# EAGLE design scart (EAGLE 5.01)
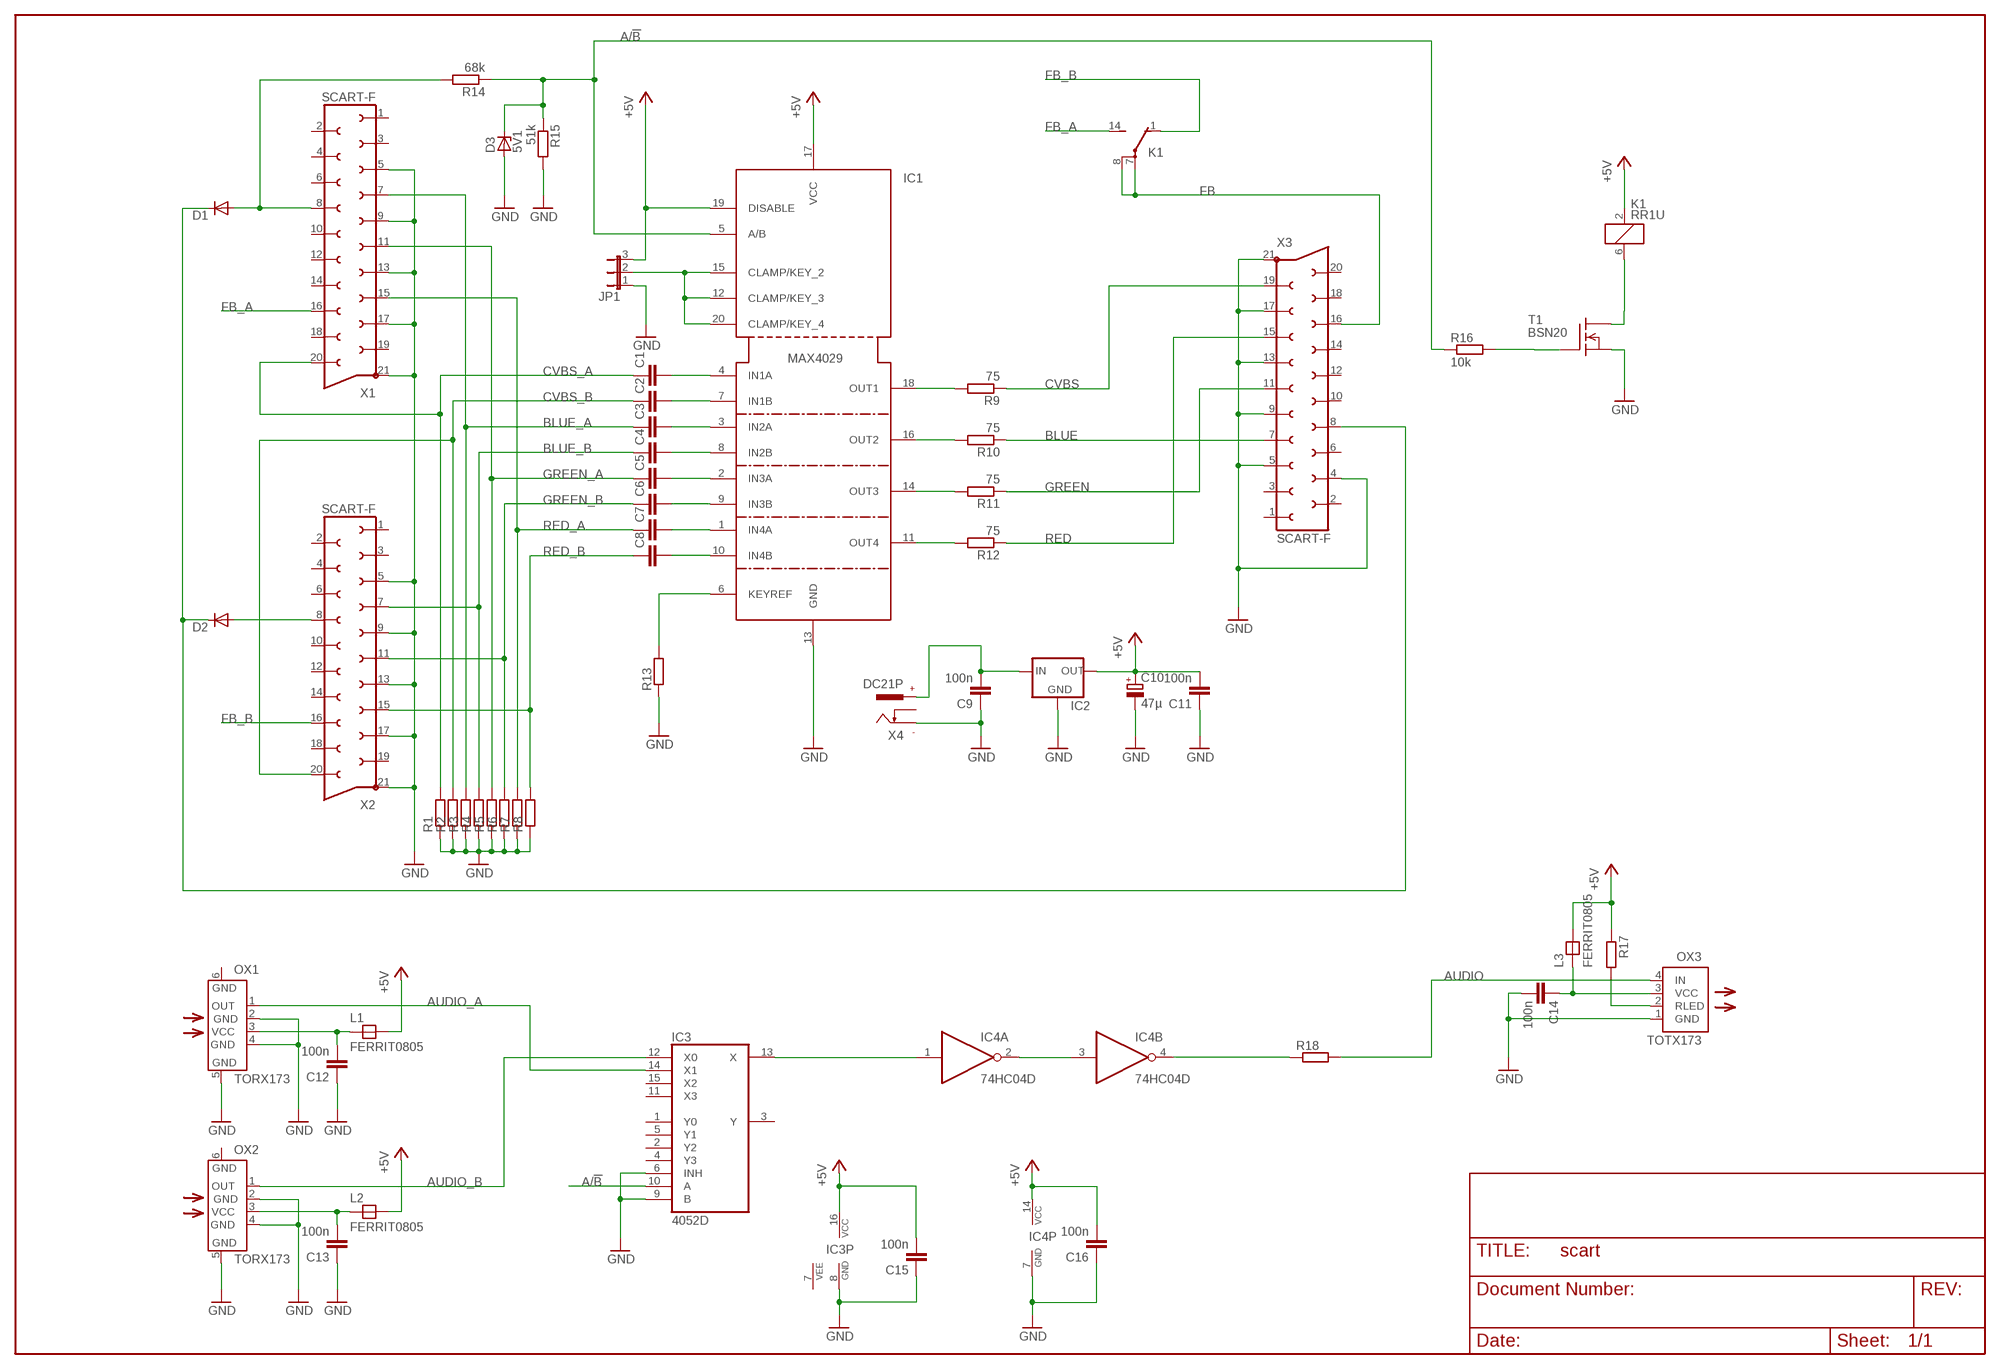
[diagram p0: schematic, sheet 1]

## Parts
C1  C-EUC0805  [C0805]
C2  C-EUC0805  [C0805]
C3  C-EUC0805  [C0805]
C4  C-EUC0805  [C0805]
C5  C-EUC0805  [C0805]
C6  C-EUC0805  [C0805]
C7  C-EUC0805  [C0805]
C8  C-EUC0805  [C0805]
C9  100n  C-EUC0805  [C0805]
C10  47µ  CPOL-EUD/7343-31W  [D/7343-31W]
C11  100n  C-EUC0805  [C0805]
C12  100n  C-EUC0805  [C0805]
C13  100n  C-EUC0805  [C0805]
C14  100n  C-EUC0805  [C0805]
C15  100n  C-EUC0805  [C0805]
C16  100n  C-EUC0805  [C0805]
D1  DIODE-MINIMELF  [MINIMELF]
D2  DIODE-MINIMELF  [MINIMELF]
D3  5V1  ZENER-DIODESOT23  [SOT23]
IC1  MAX4029EWP  [SO20L]
IC2  78XXL  [78XXL]
IC3  4052D  [SO16]
IC4  74HC04D  [SO14]
JP1  JP2E  [JP2]
K1  RR1U  [RR1U]
L1  FERRIT0805  [0805]
L2  FERRIT0805  [0805]
L3  FERRIT0805  [0805]
OX1  TORX173  [TORX173]
OX2  TORX173  [TORX173]
OX3  TOTX173  [TOTX173]
R1  R-EU_R1206  [R1206]
R2  R-EU_R1206  [R1206]
R3  R-EU_R1206  [R1206]
R4  R-EU_R1206  [R1206]
R5  R-EU_R1206  [R1206]
R6  R-EU_R1206  [R1206]
R7  R-EU_R1206  [R1206]
R8  R-EU_R1206  [R1206]
R9  75  R-EU_R1206  [R1206]
R10  75  R-EU_R1206  [R1206]
R11  75  R-EU_R1206  [R1206]
R12  75  R-EU_R1206  [R1206]
R13  R-EU_R0805  [R0805]
R14  68k  R-EU_R0805  [R0805]
R15  51k  R-EU_R0805  [R0805]
R16  10k  R-EU_R0805  [R0805]
R17  R-EU_R0805  [R0805]
R18  R-EU_R0805  [R0805]
T1  BSN20  [SOT23]
X1  SCART-F  [SCART-F]
X2  SCART-F  [SCART-F]
X3  SCART-F  [SCART-F]
X4  DC21P  [DCSKTP]

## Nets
+5V: C10.+ C11.2 C15.2 C16.2 IC1.17(VCC) IC1.19(DISABLE) IC2.OUT IC3.16(VCC) IC4.14(P:VCC) JP1.3 K1.2 L1.2 L2.2 L3.2 R17.1
A/!B!: D3.3(C) IC1.5(A/B) IC3.10(A) R14.1 R15.1 R16.1
AUDIO: OX3.4(IN) R18.2
AUDIO_A: IC3.14(X1) OX1.1(OUT)
AUDIO_B: IC3.12(X0) OX2.1(OUT)
BLUE: R10.1 X3.7
BLUE_A: C3.1 R3.2 X1.7
BLUE_B: C4.1 R4.2 X2.7
CVBS: R9.1 X3.19
CVBS_A: C1.1 R1.2 X1.20
CVBS_B: C2.1 R2.2 X2.20
FB: K1.7(2:P) K1.8(2:P) X3.16
FB_A: K1.14(2:S) X1.16
FB_B: K1.1(2:O) X2.16
GND: C9.1 C10.- C11.1 C12.1 C13.1 C14.2 C15.1 C16.1 D3.1(A) IC1.13(GND) IC2.GND IC3.6(INH) IC3.8(GND) IC3.9(B) IC4.7(P:GND) JP1.1 OX1.2(GND) OX1.4(GND) OX1.5(GND) OX2.2(GND) OX2.4(GND) OX2.5(GND) OX3.1(GND) R1.1 R2.1 R3.1 R4.1 R5.1 R6.1 R7.1 R8.1 R13.1 R15.2 T1.2(S) X1.5 X1.9 X1.13 X1.17 X1.21 X2.5 X2.9 X2.13 X2.17 X2.21 X3.4 X3.5 X3.9 X3.13 X3.17 X3.21 X4.-
GREEN: R11.1 X3.11
GREEN_A: C5.1 R5.2 X1.11
GREEN_B: C6.1 R6.2 X2.11
N$1: C8.2 IC1.10(IN4B)
N$2: C7.2 IC1.1(IN4A)
N$3: C6.2 IC1.9(IN3B)
N$4: C5.2 IC1.2(IN3A)
N$5: C4.2 IC1.8(IN2B)
N$6: C3.2 IC1.3(IN2A)
N$7: C2.2 IC1.7(IN1B)
N$8: C1.2 IC1.4(IN1A)
N$17: C9.2 IC2.IN X4.+
N$18: D2.A X2.8
N$19: IC1.18(OUT1) R9.2
N$20: IC1.16(OUT2) R10.2
N$21: IC1.14(OUT3) R11.2
N$22: IC1.11(OUT4) R12.2
N$27: D1.A R14.2 X1.8
N$29: IC1.6(KEYREF) R13.2
N$30: IC1.12(CLAMP/KEY_3) IC1.15(CLAMP/KEY_2) IC1.20(CLAMP/KEY_4) JP1.2
N$31: D1.C D2.C X3.8
N$32: C13.2 L2.1 OX2.3(VCC)
N$33: K1.6 T1.3(D)
N$35: R16.2 T1.1(G)
N$36: C12.2 L1.1 OX1.3(VCC)
N$37: C14.1 L3.1 OX3.3(VCC)
N$43: OX3.2(RLED) R17.2
N$44: IC3.13(X) IC4.1(A:I)
N$45: IC4.2(A:O) IC4.3(B:I)
N$47: IC4.4(B:O) R18.1
RED: R12.1 X3.15
RED_A: C7.1 R7.2 X1.15
RED_B: C8.1 R8.2 X2.15
Unconnected: IC3.1(Y0) IC3.2(Y2) IC3.3(Y) IC3.4(Y3) IC3.5(Y1) IC3.11(X3) IC3.15(X2) IC4.5(C:I) IC4.6(C:O) IC4.8(D:O) IC4.9(D:I) IC4.10(E:O) IC4.11(E:I) IC4.12(F:O) IC4.13(F:I) X1.1 X1.2 X1.3 X1.4 X1.6 X1.10 X1.12 X1.14 X1.18 X1.19 X2.1 X2.2 X2.3 X2.4 X2.6 X2.10 X2.12 X2.14 X2.18 X2.19 X3.1 X3.2 X3.3 X3.6 X3.10 X3.12 X3.14 X3.18 X3.20 X4.C

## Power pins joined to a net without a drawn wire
GND: OX1.6(GND) OX2.6(GND)
VEE: IC3.7(VEE)

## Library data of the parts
C1-C9 C11-C16 = rcl:C-EU: CAPACITOR, European symbol
C10 = rcl:CPOL-EU: POLARIZED CAPACITOR, European symbol
D1 D2 = diode:DIODE-: DIODE
D3 = diode:ZENER-DIODE: Z-Diode
IC1 = maxim:MAX4029
IC2 = v-reg:78XXL: VOLTAGE REGULATOR
IC3 = 40xx:4052: Dual 4-channel ANALOG MULTIPLEXER
IC4 = 74xx-eu:74*04: Hex INVERTER
JP1 = jumper:JP2E: JUMPER
K1 = relay:RR1U: RELAY reed, polarity, 1 x switch with shield
L1-L3 = Passive:FERRIT: FERRIT Universalsymbol in diversen Bauformen
OX1 OX2 = toshiba:TORX173: FIBER OPTIC RECEIVING MODULE FOR DIGITAL AUDIO EQUIPMENT, TTL Interface TORX173.pdf
OX3 = toshiba:TOTX173: FIBER OPTIC TRANSMITTING MODULE FOR DIGITAL AUDIO EQUIPMENT; TTL Interface TOTX173.pdf
R1-R18 = rcl:R-EU_: RESISTOR, European symbol
T1 = Aktive:BSN20
X1-X3 = con-hirschmann:SCART-F: TV SCART CONNECTOR
X4 = dcsocket:DC21P: DC 2.1 mm Power Socket Positive Centre

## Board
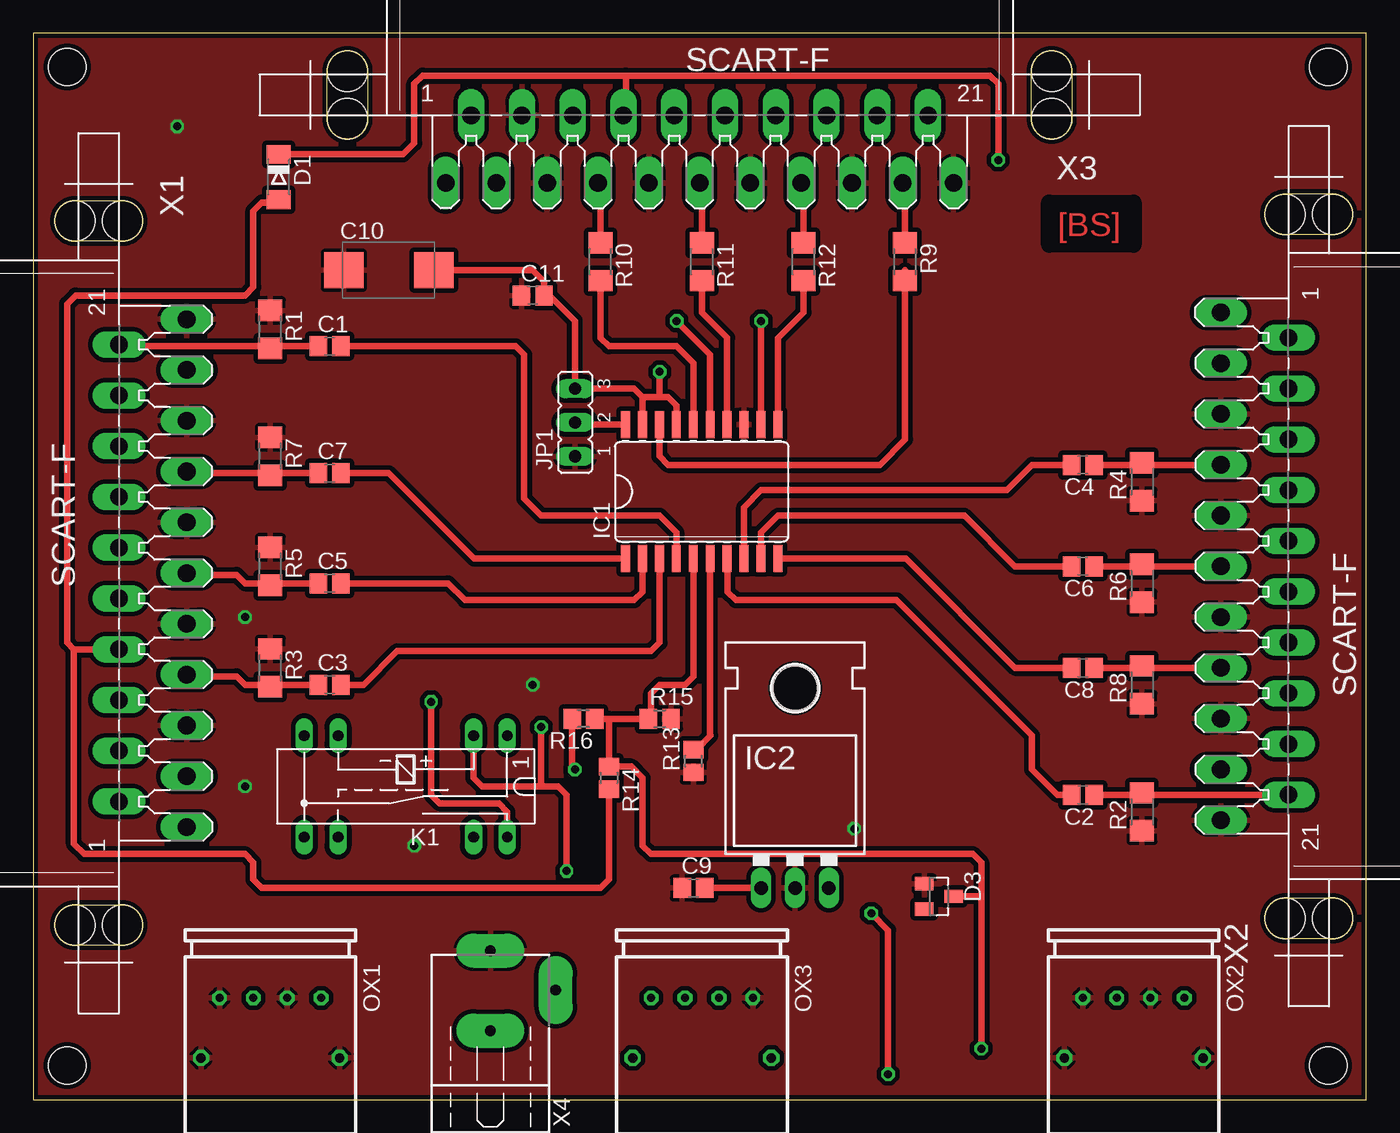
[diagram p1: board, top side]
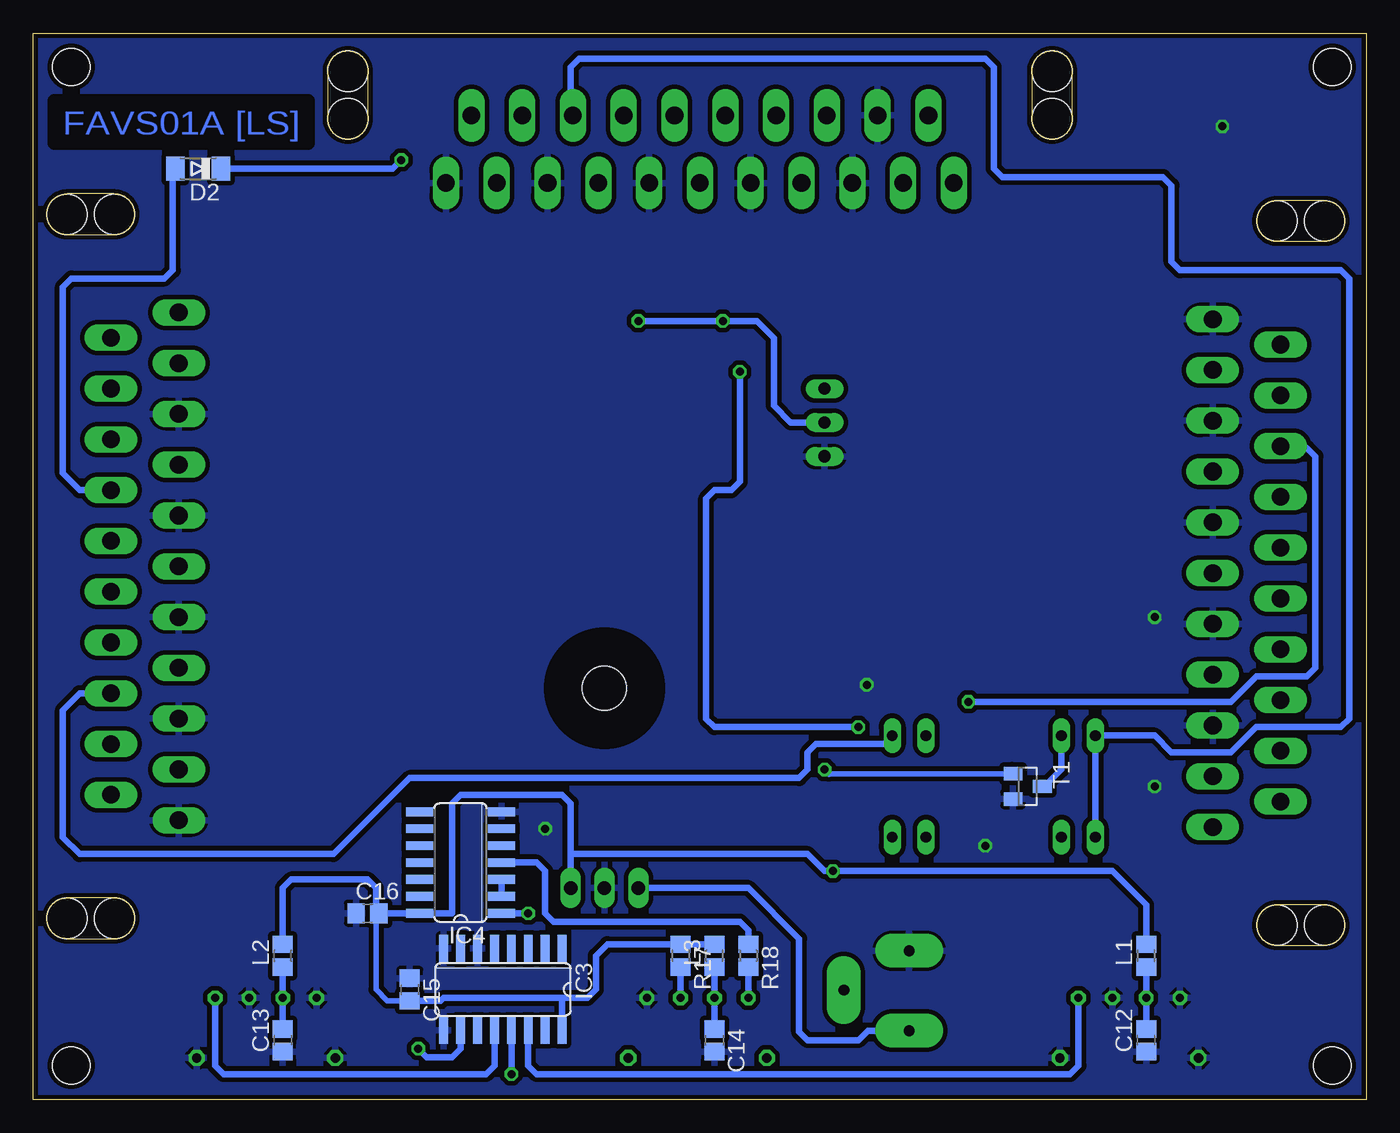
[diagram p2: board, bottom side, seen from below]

Size 100 x 80 mm. Coordinates in mm from the lower left corner, seen from the top.
Outline: 0,0 100,0 100,80 0,80 0,0
Copper layers (1*16): Top 0.035mm / dielectric 1.5mm / Bottom 0.035mm
Design rules "default": minimum track width 10mil, minimum drill 0.3mm, track to track 0.3mm, track to pad 0.3mm, pad to pad 0.3mm, via to via 0.3mm, smd to smd 0.2mm, copper to edge 0.1mm, drill to drill 8mil, minimum pad ring 10mil, minimum via ring 8mil, stop-mask expansion 4mil, vias tented up to drill 0mil, thermal gap 10mil
Holes 2.8 mm at 2.54,77.47 2.54,2.54 97.16,2.54 97.16,77.47
tRestrict: area 76.2,64.1 to 82.5,67.3
bRestrict: area 79.4,71.8 to 98.4,74.9

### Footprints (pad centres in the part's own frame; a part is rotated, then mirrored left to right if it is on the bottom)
C0805 = smd 1.3 x 1.5: 1 -0.85,0; 2 0.85,0
D/7343-31W = smd 2.95 x 2.7: + 3.375,0; - -3.375,0
MINIMELF = smd 1.4 x 1.8: A 1.7,0; C -1.7,0
SOT23 = smd 1 x 1.4: 1 -0.95,-1.1; 2 0.95,-1.1; 3 0,1.1
SO20L = smd 0.66 x 2.032: 1 -5.715,-5.029; 2 -4.445,-5.029; 3 -3.175,-5.029; 4 -1.905,-5.029; 5 -0.635,-5.029; 6 0.635,-5.029; 7 1.905,-5.029; 8 3.175,-5.029; 9 4.445,-5.029; 10 5.715,-5.029; 11 5.715,5.029; 12 4.445,5.029; 13 3.175,5.029; 14 1.905,5.029; 15 0.635,5.029; 16 -0.635,5.029; 17 -1.905,5.029; 18 -3.175,5.029; 19 -4.445,5.029; 20 -5.715,5.029
78XXL = drill 1.016 long: GND 0,-3.81; IN -2.54,-3.81; OUT 2.54,-3.81 | hole 3.302: 0,11.176
SO16 = smd 0.66 x 2.032: 1 -4.445,-3.073; 2 -3.175,-3.073; 3 -1.905,-3.073; 4 -0.635,-3.073; 5 0.635,-3.073; 6 1.905,-3.073; 7 3.175,-3.073; 8 4.445,-3.073; 9 4.445,3.073; 10 3.175,3.073; 11 1.905,3.073; 12 0.635,3.073; 13 -0.635,3.073; 14 -1.905,3.073; 15 -3.175,3.073; 16 -4.445,3.073
SO14 = smd 0.66 x 2.032: 1 -3.81,-3.073; 2 -2.54,-3.073; 3 -1.27,-3.073; 4 0,-3.073; 5 1.27,-3.073; 6 2.54,-3.073; 7 3.81,-3.073; 8 3.81,3.073; 9 2.54,3.073; 10 1.27,3.073; 11 0,3.073; 12 -1.27,3.073; 13 -2.54,3.073; 14 -3.81,3.073
JP2 = drill 0.914 long: 1 -2.54,0; 2 0,0; 3 2.54,0
RR1U = drill 0.813 long: 1 -7.62,-3.81; 2 -5.08,-3.81; 6 5.08,-3.81; 7 7.62,-3.81; 8 7.62,3.81; 9 5.08,3.81; 13 -5.08,3.81; 14 -7.62,3.81
0805 = smd 1.3 x 1.5: 1 -0.85,0; 2 0.85,0
TORX173 = drill 0.6 octagon: 1 -3.81,0; 2 -1.27,0; 3 1.27,0; 4 3.81,0 | drill 0.7 octagon: 5 5.2,4.5; 6 -5.2,4.5
TOTX173 = drill 0.6 octagon: 1 -3.81,0; 2 -1.27,0; 3 1.27,0; 4 3.81,0 | drill 0.7 octagon: 5 5.2,4.5; 6 -5.2,4.5
R1206 = smd 1.6 x 1.803: 1 -1.422,0; 2 1.422,0
R0805 = smd 1.3 x 1.5: 1 -0.85,0; 2 0.85,0
SCART-F = drill 1.321 long: 1 19.05,5.08; 2 17.145,0; 3 15.24,5.08; 4 13.335,0; 5 11.43,5.08; 6 9.525,0; 7 7.62,5.08; 8 5.715,0; 9 3.81,5.08; 10 1.905,0; 11 0,5.08; 12 -1.905,0; 13 -3.81,5.08; 14 -5.715,0; 15 -7.62,5.08; 16 -9.525,0; 17 -11.43,5.08; 18 -13.335,0; 19 -15.24,5.08; 20 -17.145,0; 21 -19.05,5.08 | hole 3.023: 26.416,0.254; 26.416,-3.302; -26.416,0.254; -26.416,-3.302
DCSKTP = drill 0.813 pad 2.54 long: + -1.27,0.08; - -1.27,6.08; C 3.63,3.13

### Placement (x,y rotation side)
C1  22.23,56.52 0 top
C2  78.74,22.86 180 top
C3  22.23,31.11 0 top
C4  78.74,47.62 180 top
C5  22.23,38.73 0 top
C6  78.74,40.01 180 top
C7  22.23,46.99 0 top
C8  78.74,32.38 180 top
C9  49.53,15.88 0 top
C10  26.67,62.23 0 top
C11  37.47,60.33 0 top
C12  16.51,4.45 90 bottom
C13  81.28,4.45 90 bottom
C14  48.9,4.45 270 bottom
C15  71.75,8.26 270 bottom
C16  74.93,13.97 0 bottom
D1  18.41,69.22 270 top
D2  87.63,69.85 180 bottom
D3  67.94,15.24 270 top
IC1  50.15,45.61 0 top
IC2  57.15,19.68 0 top
IC3  64.77,8.26 180 bottom
IC4  67.94,17.78 90 bottom
JP1  40.64,50.8 90 top
K1  27.94,23.5 180 top
L1  16.51,10.79 90 bottom
L2  81.28,10.79 90 bottom
L3  48.9,10.79 90 bottom
OX1  17.78,7.62 180 top
OX2  82.55,7.62 180 top
OX3  50.16,7.62 180 top
R1  17.78,57.78 270 top
R2  83.19,21.59 90 top
R3  17.78,32.38 270 top
R4  83.19,46.35 90 top
R5  17.78,40.01 270 top
R6  83.19,38.73 90 top
R7  17.78,48.26 270 top
R8  83.19,31.11 90 top
R9  65.41,62.87 270 top
R10  42.55,62.87 270 top
R11  50.16,62.87 270 top
R12  57.78,62.87 270 top
R13  49.53,25.4 90 top
R14  43.18,24.13 270 top
R15  46.99,28.57 0 top
R16  41.27,28.57 180 top
R17  51.44,10.79 270 bottom
R18  46.35,10.79 270 bottom
T1  25.4,23.5 270 bottom
X1  6.43,39.5 270 top
X2  94.17,40.01 90 top
X3  49.99,73.85 180 top
X4  35.56,5.08 0 top

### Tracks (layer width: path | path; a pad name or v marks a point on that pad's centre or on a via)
+5V  (via drill 0.6)
  Top 0.5: 45.7,52.72 IC1.19 | 45.7,52.72 45.09,53.34 JP1.3 40.64,58.42 38.73,60.33 C11.2 38.31,61.38 37.47,62.23 C10.+ | IC1.17 48.24,52.09 47.62,52.7 46.99,52.7 | 45.7,52.72 45.7,52.7 46.99,52.7 | v40.01,17.14 40.01,22.86 39.37,23.5 38.1,23.5 | 38.1,23.5 33.66,23.5 33.02,24.13 K1.2 | 38.1,23.5 v38.1,27.94 | v46.99,54.61 46.99,52.7
  Bottom 0.406: C15.2 73.44,7.41 74.3,8.26 74.3,13.97
  Bottom 0.5: L1.2 16.51,14.61 19.05,17.14 v40.01,17.14 40.64,17.14 41.91,18.41 59.69,18.41 IC2.OUT 59.69,22.23 60.33,22.86 67.94,22.86 68.58,22.23 68.58,13.97 71.12,13.97 | L2.2 81.28,15.88 80.64,16.51 74.93,16.51 74.3,15.88 74.3,13.97 C16.2 71.12,13.97 | 71.12,13.97 IC4.14 | 60.33,7.62 IC3.16 | C15.2 69.43,7.41 69.22,7.62 60.33,7.62 | 60.33,7.62 58.42,7.62 57.78,8.26 57.78,10.79 56.94,11.64 R17.1 49.11,11.64 48.9,11.43 L3.2 | v38.1,27.94 48.9,27.94 49.53,28.57 49.53,45.09 48.9,45.72 47.62,45.72 46.99,46.35 v46.99,54.61
A/!B!  (via drill 0.6)
  Top 0.5: 43.18,28.57 R16.1 | 43.18,28.57 R15.1 46.35,28.57 46.35,30.48 46.99,31.11 48.9,31.11 49.53,31.75 49.53,40.64 49.51,40.64 IC1.5 | 43.18,28.57 R14.1 44.87,24.98 45.72,24.13 45.72,19.05 46.35,18.41 70.48,18.41 71.12,17.78 71.12,15.24 | 71.12,15.24 v71.12,3.81 | 71.12,15.24 D3.3
  Bottom 0.5: IC3.10 67.94,3.81 68.58,3.17 70.48,3.17 v71.12,3.81
AUDIO
  Bottom 0.5: R18.2 OX3.4
AUDIO_A
  Bottom 0.5: IC3.14 62.87,2.54 62.23,1.91 22.23,1.91 21.59,2.54 OX1.1
AUDIO_B
  Bottom 0.5: IC3.12 65.41,2.54 66.04,1.91 85.72,1.91 86.36,2.54 OX2.1
BLUE
  Top 0.5: X3.7 42.37,68.58 42.55,68.58 R10.1
BLUE_A
  Top 0.5: 21.59,31.11 21.17,31.54 | 21.59,31.11 C3.1 | 11.51,31.75 11.43,31.75 | X1.7 11.51,31.75 | 11.51,31.75 15.24,31.75 15.88,31.11 17.78,31.11 | 17.78,31.11 R3.2 | 17.78,31.11 21.59,31.11
BLUE_B
  Top 0.5: X2.7 88.9,47.63 88.9,47.62 83.19,47.62 | 79.38,47.62 C4.1 83.19,47.62 | 83.19,47.62 R4.2
CVBS
  Top 0.5: X3.19 65.23,68.58 65.41,68.58 R9.1
CVBS_A
  Top 0.5: 21.59,56.52 C1.1 17.78,56.52 | 6.43,56.52 6.35,56.52 | X1.20 6.43,56.52 | 6.43,56.52 17.78,56.52 | 17.78,56.52 R1.2
CVBS_B
  Top 0.5: 79.38,22.86 C2.1 83.19,22.86 | 83.19,22.86 R2.2 | X2.20 83.19,22.86
FB
  Bottom 0.5: K1.8 K1.7 15.88,27.3 14.61,26.04 10.16,26.04 8.26,27.94 1.91,27.94 1.27,28.57 1.27,61.59 1.91,62.23 13.97,62.23 14.61,62.87 14.61,68.58 15.24,69.22 27.3,69.22 27.94,69.85 27.94,77.47 28.57,78.11 59.05,78.11 59.69,77.47 59.69,73.66 59.52,73.66 X3.16
FB_A  (via drill 0.6)
  Top 0.5: v29.84,29.84 29.84,22.86 30.48,22.23 34.92,22.23 35.56,21.59 K1.14
  Bottom 0.5: v29.84,29.84 10.16,29.84 8.26,31.75 4.45,31.75 3.81,32.38 3.81,48.26 4.45,48.9 6.43,48.9 X1.16
FB_B
  Bottom 0.5: X2.16 93.98,30.48 96.52,30.48 97.79,29.21 97.79,19.68 96.52,18.41 77.47,18.41 71.75,24.13 42.55,24.13 41.91,24.77 41.91,26.04 41.27,26.67 36.2,26.67 K1.1
GND  (via drill 0.6)
  other vias: 37.47,31.11 61.59,20.32 15.88,36.2 15.88,23.5 10.79,73.03 28.57,19.05
  pour Top (isolate 0.35): 0,80.01 100.33,80.01 100.33,0 0,0
  pour Bottom (isolate 0.35): 0,80.01 0,0 100.33,0 100.33,80.01
GREEN
  Top 0.5: X3.11 49.99,68.58 50.16,68.58 R11.1
GREEN_A
  Top 0.5: 21.59,38.73 21.17,39.16 | 21.59,38.73 C5.1 | 11.51,39.37 11.43,39.37 | X1.11 11.51,39.37 | 11.51,39.37 15.24,39.37 15.88,38.73 17.78,38.73 | 17.78,38.73 R5.2 | 17.78,38.73 21.59,38.73
GREEN_B
  Top 0.5: X2.11 88.9,40.01 83.19,40.01 | 79.38,40.01 C6.1 83.19,40.01 | 83.19,40.01 R6.2
N$1
  Top 0.5: IC1.10 65.46,40.58 73.66,32.38 C8.2 78.11,32.38
N$2
  Top 0.5: C7.2 26.67,46.99 33.08,40.58 IC1.1
N$3
  Top 0.5: IC1.9 54.59,42.53 55.88,43.81 69.85,43.81 73.66,40.01 C6.2 78.11,40.01
N$4
  Top 0.5: IC1.2 45.7,38.08 45.09,37.47 32.38,37.47 31.11,38.73 C5.2 22.86,38.73
N$5
  Top 0.5: IC1.8 53.32,44.43 54.61,45.72 73.03,45.72 74.93,47.62 C4.2 78.11,47.62
N$6
  Top 0.5: 22.86,31.11 C3.2 24.77,31.11 27.3,33.66 46.35,33.66 46.99,34.29 46.99,40.64 46.97,40.64 IC1.3
N$7
  Top 0.5: C2.2 76.83,22.86 74.93,24.77 74.93,27.3 64.77,37.47 52.7,37.47 52.07,38.1 52.07,40.64 52.05,40.64 IC1.7
N$8
  Top 0.5: IC1.4 48.24,42.56 46.99,43.81 38.1,43.81 36.83,45.09 36.83,55.88 36.2,56.52 C1.2 22.86,56.52
N$17
  Top 0.5: IC2.IN C9.2
  Bottom 0.5: X4.+ 37.38,5.16 38.1,4.45 41.91,4.45 42.55,5.08 42.55,12.06 46.35,15.88 IC2.IN
N$18
  Bottom 0.5: X2.8 96.53,45.73 97.79,46.99 97.79,60.96 97.16,61.59 90.17,61.59 89.53,62.23 89.53,69.85 D2.A
N$19
  Top 0.5: IC1.18 46.97,48.28 47.62,47.62 63.5,47.62 65.41,49.53 R9.2 65.41,62.23
N$20
  Top 0.5: IC1.16 49.51,55.26 48.26,56.52 43.18,56.52 42.55,57.15 R10.2
N$21
  Top 0.5: IC1.14 52.05,57.17 50.16,59.05 R11.2 50.16,61.59
N$22
  Top 0.5: IC1.11 55.86,57.13 57.78,59.05 R12.2 57.78,61.59
N$27
  Top 0.5: 3.04,33.78 X1.8 | 3.04,33.78 2.54,34.29 2.54,59.69 3.17,60.33 15.88,60.33 16.51,60.96 16.51,66.67 17.14,67.31 18.41,67.31 D1.A | 3.04,33.78 3.04,19.18 3.81,18.41 15.88,18.41 16.51,17.78 16.51,16.51 17.14,15.88 42.55,15.88 43.18,16.51 R14.2 43.18,23.5
N$29
  Top 0.5: IC1.6 50.78,27.3 50.8,27.3 49.74,26.25 R13.2
N$30  (via drill 0.6)
  Top 0.5: IC1.20 40.8,50.64 JP1.2 | IC1.15 50.78,55.9 v48.26,58.42 | IC1.12 54.59,58.4 v54.61,58.42
  Bottom 0.5: JP1.2 43.18,50.8 44.45,52.07 44.45,57.15 45.72,58.42 v48.26,58.42 v54.61,58.42
N$31  (via drill 0.6)
  Top 0.5: v72.39,70.48 72.39,76.2 71.75,76.83 44.45,76.83 | X3.8 44.27,73.66 44.45,73.66 44.45,76.83 | D1.C 27.73,70.92 28.57,71.75 28.57,76.2 29.21,76.83 44.45,76.83
  Bottom 0.5: D2.C 73.03,69.85 v72.39,70.48
N$32
  Bottom 0.5: C13.2 OX2.3 L2.1
N$33
  Bottom 0.406: T1.3 24.13,23.5
  Bottom 0.5: 24.13,23.5 22.86,24.77 K1.6
N$35  (via drill 0.6)
  Top 0.5: R16.2 40.42,24.98 v40.64,24.77
  Bottom 0.406: T1.1 26.5,24.77 26.67,24.77 26.99,24.45 40.32,24.45
  Bottom 0.5: 40.32,24.45 v40.64,24.77
N$36
  Bottom 0.5: L1.1 OX1.3 C12.2 16.51,5.08
N$37
  Bottom 0.5: L3.1 OX3.3 C14.1
N$43
  Bottom 0.5: R17.2 OX3.2
N$44  (via drill 0.6)
  Top 0.5: v64.14,1.91 64.14,12.7 v62.87,13.97
  Bottom 0.5: v64.14,1.91 IC3.13 | v62.87,13.97 IC4.1
N$45
  Bottom 0.5: IC4.2 64.77,15.24 64.87,15.34 IC4.3
N$47
  Bottom 0.5: R18.1 46.35,12.7 46.99,13.34 60.96,13.34 61.59,13.97 61.59,17.14 62.23,17.78 IC4.4
RED
  Top 0.5: X3.15 57.61,68.58 57.78,68.58 R12.1
RED_A
  Top 0.5: 21.59,46.99 21.17,47.41 | 21.59,46.99 C7.1 | 11.51,46.99 11.43,46.99 | X1.15 11.51,46.99 | 11.51,46.99 17.78,46.99 | 17.78,46.99 R7.2 | 17.78,46.99 21.59,46.99
RED_B
  Top 0.5: X2.15 88.9,32.39 88.9,32.38 83.19,32.38 | 79.38,32.38 C8.1 83.19,32.38 | 83.19,32.38 R8.2

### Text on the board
Top: [BS]
Bottom: FAVS01A [LS]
